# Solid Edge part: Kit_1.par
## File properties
Author: bmolnar
Last saved by: bmolnar
Revision: 77
Sűrűség: 0,000 kg/m^3
Pontosság: 0,990
Username: bmolnar
Dokumentum tartalom típus: 0
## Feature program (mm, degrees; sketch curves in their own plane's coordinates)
base feature "unnamed BaseFeature 1"
sketch for "unnamed Hole 1" plane through (0, 0, 19.5) normal (0, 0, 1) x-axis (0, -1, 0)
  hole centre (-44.5, 44.5) bore radius 4.188
hole "unnamed Hole 1" through
sketch for "unnamed Hole 2" plane through (0, 0, 19.5) normal (0, 0, 1) x-axis (0, -1, 0)
  hole centre (44.5, 44.5) bore radius 4.188
hole "unnamed Hole 2" through
sketch for "unnamed Hole 3" plane through (0, 0, 19.5) normal (0, 0, 1) x-axis (0, -1, 0)
  hole centre (44.5, -44.5) bore radius 4.188
hole "unnamed Hole 3" through
sketch for "unnamed Hole 4" plane through (0, 0, 19.5) normal (0, 0, 1) x-axis (0, -1, 0)
  hole centre (-44.5, -44.5) bore radius 4.188
hole "unnamed Hole 4" through
pattern "unnamed Pattern 1" of "unnamed Hole 1", "unnamed Hole 2", "unnamed Hole 3", "unnamed Hole 4"
sketch for "Furat_6" plane through (56.65, 0, 56.65) normal (-1, 0, 0) x-axis (0, -1, 0)
  hole centre (0, -47.65) bore radius 4.283
hole "Furat_6" nominal diameter 9.728 finite  ThreadDepth = 12 mm
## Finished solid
Body 1: solid body, 293 faces, 720 edges, 444 vertices.
  Faces by surface: plane 143, cylinder 70, swept 56, cone 15, torus 8, spline 1
  Edges by curve: line 430, circle 140, spline 120, ellipse 28, curve on surface 2
Bounding box of the edges (mm; curved faces can reach further): 113.300 x 113.300 x 19.500, from (-56.65, -56.65, 0) to (56.65, 56.65, 19.5).
Cylindrical faces by radius (mm): R0.2 x48, R0.2006 x2, R0.2007 x2, R4.188 x4, R4.283 x1, R6 x1, R6.35 x4, R6.55 x4, R6.75 x4
Conical faces (half-angle, radius in mm at the cone's reference point): 0.5 deg R12.25 x4, 0.5 deg R35 x2, 45 deg R4.185 x4, 45 deg R4.985 x4, 45 deg R6.25 x1
Toroidal faces (ring radius, tube radius in mm): R6.05 r0.3 x2, R6.15 r0.2 x6
Planar faces by outward normal: +x 17, +y 16, +z 18, -x 14, -y 14, -z 1, oblique 63
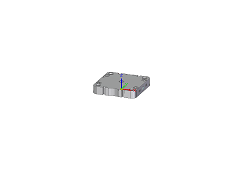
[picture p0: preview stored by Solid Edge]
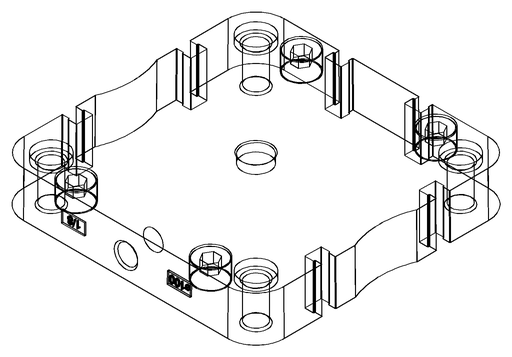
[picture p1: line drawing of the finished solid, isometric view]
